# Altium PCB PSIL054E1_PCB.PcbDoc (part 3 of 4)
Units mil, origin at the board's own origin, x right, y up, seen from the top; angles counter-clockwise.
Board outline 2080 x 2700 mil, 8 copper layers (SSTXRX1, GND Plane 1, High Speed, GND Plane 2, Power 1, Power 2, GND Plane 3, SSTXRX2), stack 58.12 mil thick; 247 components, 148 nets, 834 pads, 632 vias.
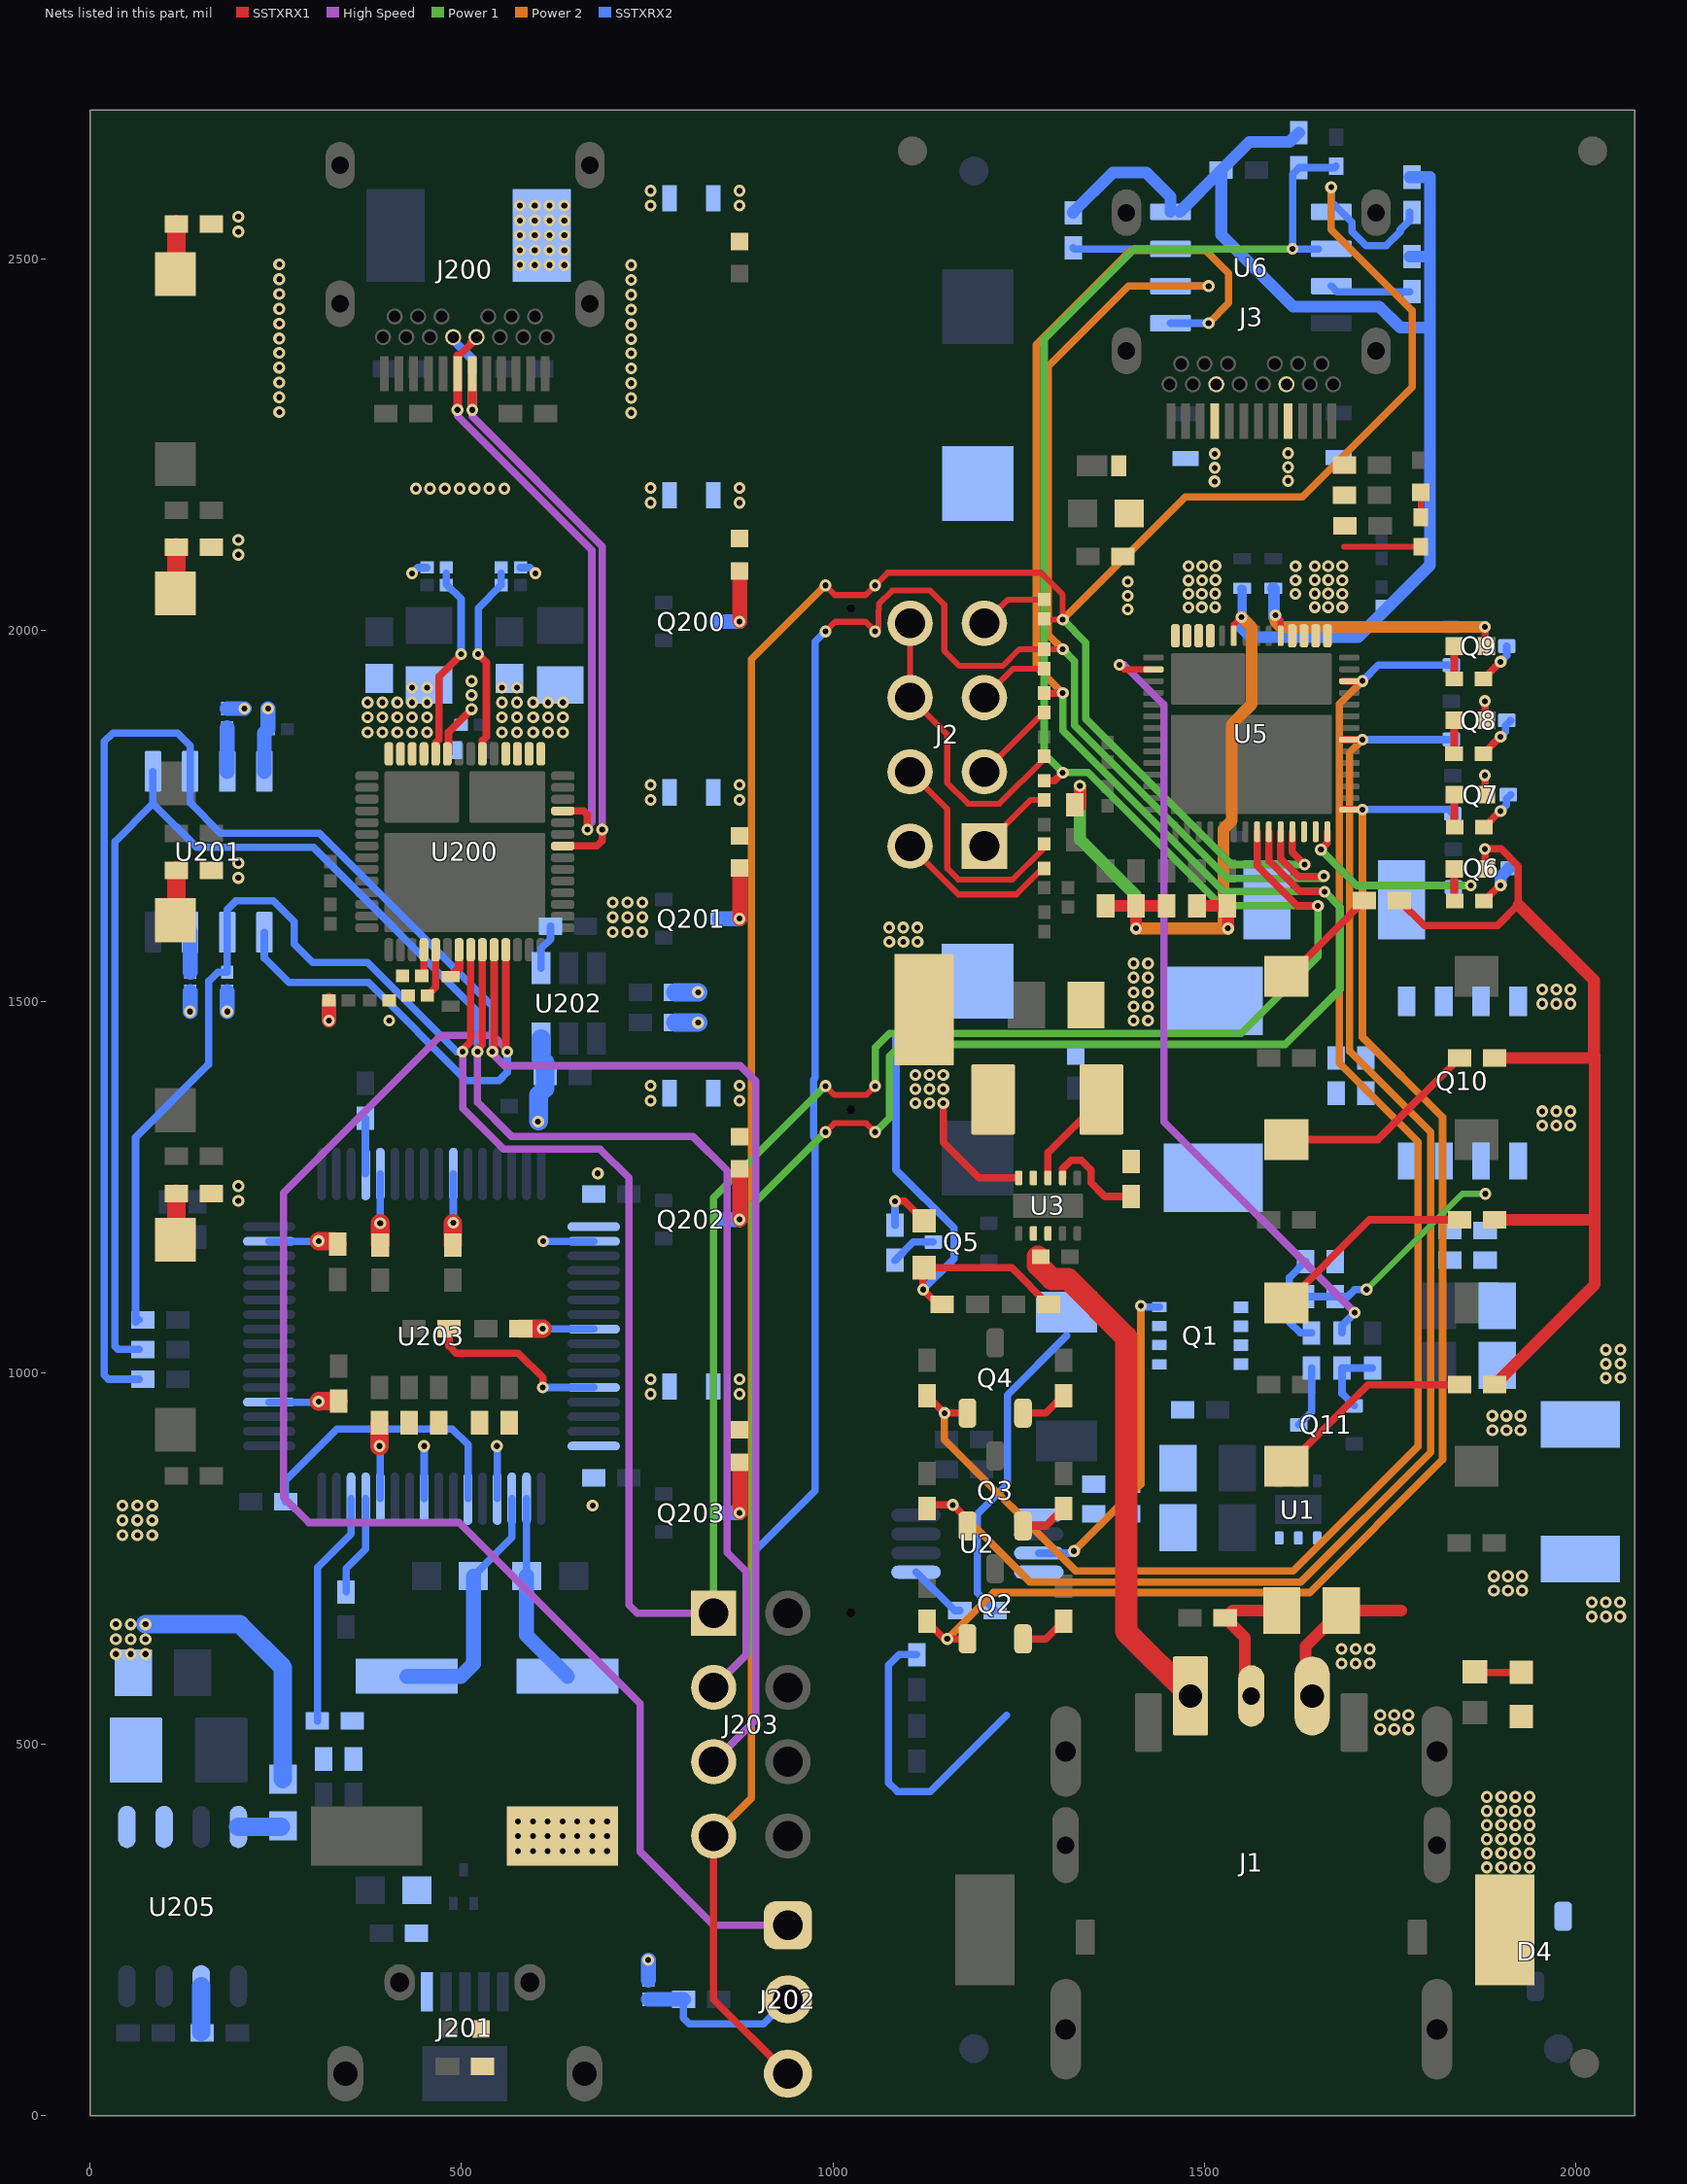
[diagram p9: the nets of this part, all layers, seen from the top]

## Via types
v1: diameter 16, hole 8, SSTXRX1 to SSTXRX2, tented both sides, 581 vias
v2: diameter 19.68, hole 7.87, SSTXRX1 to SSTXRX2, tented both sides, 51 vias

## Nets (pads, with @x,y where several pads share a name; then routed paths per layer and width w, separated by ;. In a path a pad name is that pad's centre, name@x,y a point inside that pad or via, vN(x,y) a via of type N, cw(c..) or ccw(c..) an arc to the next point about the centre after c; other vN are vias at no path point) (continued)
LDO_3V3: C20.1 C23.1 R36.2 R37.2 R38.2 R39.1 R40.1 R41.2 R42.1 R44.1 R45.1 R46.1 R47.2 U5.9 U6.8 | length 2771.1
  SSTXRX1 w8: U5.9@1539.88,1992.15 1539.88,2007.04 v1(1550.1,2017.26)
  SSTXRX1 w16: R36.2@1332.57,1762.63 v1(1332.57,1790.01) ; R37.2@1367.29,1628.64 R38.2@1408.29,1628.64 R46.1@1449.29,1628.64 ; v1(1408.1,1598.26) R38.2@1408.1,1628.45 ; R45.1@1490.29,1628.64 R44.1@1531.29,1628.64 1532.1,1627.83 v1(1532.1,1598.26)
  Power 1 w16: v1(1332.57,1790.01) 1332.57,1718.01 1408.1,1642.48 v1(1408.1,1598.26)
  Power 2 w16: v1(1408.1,1598.26) v1(1532.1,1598.26) 1526.1,1604.26 1526.1,1732.1 1537,1743 1537,1873 1564,1900 1564,2003.36 v1(1550.1,2017.26)
  SSTXRX2 w12: v1(1550.1,2017.26) 1551.1,2018.26 1551.1,2055.26 C23.1@1550.1,2055.26
  SSTXRX2 w16: R41.2@1323.57,2561.63 1323.57,2562.57 1377,2616 1422,2616 1454.73,2583.27 U6.8@1454.73,2563 ; U6.8@1466.94,2563 C20.1@1522.95,2619.01 ; v1(1550.1,2017.26) 1550.1,2003.26 1563.1,1990.26 1707.1,1990.26 1804,2087.16 1804,2407 ; R40.1@1627.57,2669.63 1614.94,2657 1560.94,2657 C20.1@1522.95,2619.01 ; R42.1@1776.57,2502.63 1803.63,2502.63 ; R39.1@1776.57,2609.63 1801.63,2609.63 ; 1804,2610 1804,2407 ; C20.1@1522.95,2619.01 1522.95,2532.05 1619.78,2435.22 1735.78,2435.22 1764,2407 1804,2407
LDO_3V3_SINK: C207.1 C208.1 C213.1 R201.2 R202.2 R203.1 R204.1 R205.2 R206.2 R207.2 R208.2 R209.2 R210.2 R213.2 R214.2 R215.2 R217.2 R219.2 R220.2 R221.2 R223.2 U200.9 U201.8 | length 331.7
  SSTXRX1 w10: U200.9@480.83,1833.2 482.45,1833.2 482.45,1862.31 v1(513.45,1893.31)
  SSTXRX1 w20: v1@321.46,1474.32 R201.2@321.46,1501.31
  SSTXRX2 w10: v1(433.45,2076.31) 441.14,2084 R209.2@453,2084 ; R210.2@579,2084 591.75,2084 v1(599.45,2076.31)
  SSTXRX2 w20: v1(134.45,1486.31) R208.2@134.45,1513.32 ; v1(184.45,1486.31) R206.2@184.45,1513.32 ; R207.2@184.45,1894.3 v1(207.45,1894.31) ; U201.8@234.45,1809.57 C213.1@234.45,1861.31 ; C213.1@239.45,1866.31 v1(239.45,1894.31) ; R205.2@751.45,182.31 v1(751.45,209.32)
  other v1: 754.45,971.31 754.45,991.31 199.45,1231.31 199.45,1251.31 754.45,1366.31 754.45,1386.31 321.45,1474.31 402.45,1474.31 199.45,1666.31 199.45,1686.31 754.45,1771.31 754.45,1791.31 513.45,1912.31 513.45,1931.31 199.45,2101.31 199.45,2121.31 754.45,2171.31 754.45,2191.31 199.45,2536.31 199.45,2556.31
NetC6_2: C6.2 R3.1 U2.5
NetC12_1: C12.1 C13.1 C14.1 Q10.7 Q10.8 R22.2 R24.2
  other v1: 1888.07,922.66 1907.07,922.66 1926.07,922.66 1888,942 1907,942 1926,942 2041,993 2060.34,993.07 2041,1012 2060.34,1012.07 2041,1031 2060.34,1031.07 1955.07,1332.66 1974.07,1332.66 1993.07,1332.66 1955,1352 1974,1352 1993,1352 1955.07,1496.66 1974.07,1496.66 1993.07,1496.66 1955,1516 1974,1516 1993,1516
NetC14_2: C14.2 C15.2 C16.2 Q10.2 Q10.4 R24.1 R25.1 R26.1 R27.2 | length 126.6
  SSTXRX2 w10: C15.2@1636.47,1149.77 1614.66,1127.96 1614.66,1068.28 1629.38,1053.55 R27.2@1644.66,1053.55
NetC15_1: C15.1 Q10.1 Q10.3 R25.2 | length 299.5
  Power 1 w8: v1(1718.66,1111.93) 1847.66,1240.93 v1(1878.66,1240.93)
  SSTXRX2 w10: C15.1@1636.47,1102.53 R25.2@1676.47,1102.53 1693.26,1102.53 1702.66,1111.93 v1(1718.66,1111.93)
NetC16_1: C16.1 Q10.5 Q10.6 R23.1 R26.2
NetC206_1: C206.1 U200.35 | length 40.7
  SSTXRX1 w12: C206.1@485.45,1533.31 496.57,1544.43 U200.35@496.57,1569.42
NetC227_2: C227.2 U203.2 Y200.1 | length 262.1
  SSTXRX2 w10: C227.2@587.4,726.86 U203.2@587.4,830.48
  SSTXRX2 w20: C227.2@587.4,726.86 587.4,646.62 Y200.1@642.71,591.31
NetC228_1: C228.1 J201.1 L200.1
NetC229_2: C229.2 U203.3 Y200.2 | length 340.7
  SSTXRX2 w10: C229.2@515.94,726.31 567.72,778.08 U203.3@567.72,830.48
  SSTXRX2 w20: Y200.2@426.18,591.31 499.45,591.31 515.94,607.8 C229.2@515.94,726.31
NetD2_2: D2.2 R7.2 | length 59.5
  SSTXRX1 w10: R7.2@1867.53,596.53 D2.2@1927,596.53
NetD3_1: D3.1 R8.2 | length 82.4
  SSTXRX1 w10: v1(1083.66,1230.93) 1096.15,1230.93 D3.1@1122.66,1204.43
  SSTXRX2 w10: R8.2@1083.66,1198.55 v1(1083.66,1230.93)
NetD5_2: D5.2 R18.2 | length 42.4
  SSTXRX1 w10: R18.2@1836.79,1635.88 D5.2@1836.79,1678.26
NetD6_2: D6.2 R19.2 | length 43.4
  SSTXRX1 w10: R19.2@1836.79,1734.88 D6.2@1836.79,1778.26
NetD7_2: D7.2 R20.2 | length 44.6
  SSTXRX1 w10: R20.2@1836.79,1833.64 D7.2@1836.79,1878.26
NetD8_2: D8.2 R21.2 | length 44
  SSTXRX1 w10: R21.2@1836.76,1934.26 D8.2@1836.76,1978.23
NetD9_1: D9.1 R61.1 | length 33.7
  SSTXRX1 w8: R61.1@1791.38,2151.68 D9.1@1791.38,2185.35
NetD200_1: D200.1 R200.1
  other v1: 874.45,2571.31 874.45,2591.31
NetD201_1: D201.1 R213.1
  other v1: 874.45,2171.31 874.45,2191.31
NetD201_2: D201.2 Q200.3 | length 85.1
  SSTXRX1 w20: v1(874.45,2011.31) D201.2@874.45,2068.83
  SSTXRX2 w20: Q200.3@846.85,2011.31 v1(874.45,2011.31)
NetD202_1: D202.1 R214.1
  other v1: 874.45,1771.31 874.45,1791.31
NetD202_2: D202.2 Q201.3 | length 86.1
  SSTXRX1 w20: v1(874.45,1611.31) 874.45,1668.83 D202.2@874.45,1669.81
  SSTXRX2 w20: Q201.3@846.85,1611.31 v1(874.45,1611.31)
NetD203_1: D203.1 R220.1
  other v1: 874.45,1366.31 874.45,1386.31
NetD203_2: D203.2 Q202.3 | length 85.1
  SSTXRX1 w20: v1(874.45,1206.31) D203.2@874.45,1263.83
  SSTXRX2 w20: Q202.3@846.85,1206.31 v1(874.45,1206.31)
NetD204_1: D204.1 R221.1
  other v1: 874.45,971.31 874.45,991.31
NetD204_2: D204.2 Q203.3 | length 85.1
  SSTXRX1 w20: v1(874.45,811.31) D204.2@874.45,868.83
  SSTXRX2 w20: Q203.3@846.85,811.31 v1(874.45,811.31)
NetD205_2: D205.2 R234.2
NetJ1_3: J1.3 R1.1 R2.2 | length 196.5
  SSTXRX1 w16: J1.3@1554.66,564.89 1554.66,643.55 R2.2@1528.28,669.93 1538.28,679.93 R1.1@1604.66,679.93
NetJ2_1: J2.1 R53.2 | length 106.3
  SSTXRX1 w8: J2.1@1204,1709 1266.02,1771.02 R53.2@1284.57,1771.02
NetJ2_2: J2.2 R51.2 | length 222
  SSTXRX1 w8: J2.2@1104,1709 1169,1644 1247,1644 1282,1679 R51.2@1284.57,1679
NetJ2_3: J2.3 R55.1 | length 113.7
  SSTXRX1 w8: J2.3@1204,1809 1284.02,1889.02 R55.1@1284.57,1889.02
NetJ2_4: J2.4 R50.2 | length 310.6
  SSTXRX1 w8: J2.4@1104,1809 1154,1759 1154,1679 1169,1664 1242,1664 1284.57,1706.57 R50.2@1284.57,1712.02
NetJ2_5: J2.5 R54.2 | length 96.7
  SSTXRX1 w8: J2.5@1204,1909 1243.02,1948.02 R54.2@1284.57,1948.02
NetJ2_6: J2.6 J2.8 R57.2 | length 406.4
  SSTXRX1 w8: J2.8@1104,2009 J2.6@1104,1909 1154,1859 1154,1794 1182,1766 1224,1766 1284.57,1826.57 R57.2@1284.57,1830.02
NetJ2_7: J2.7 R56.2 | length 93.8
  SSTXRX1 w8: J2.7@1204,2009 1236,2041 R56.2@1284.57,2041
NetL2_1: L2.1 U3.9
NetQ1_4: Q1.4 U2.7 | length 441.3
  Power 2 w10: v1(1324.66,759.93) 1414.66,849.93 v1(1414.66,1089.93)
  SSTXRX2 w10: U2.7@1277.33,757.14 1321.86,757.14 v1(1324.66,759.93) ; v1(1414.66,1089.93) 1416.27,1088.32 Q1.4@1439.54,1088.32
NetQ2_2: Q2.2 R14.2 | length 64.4
  SSTXRX1 w10: Q2.2@1256.06,641.69 1287.04,641.69 R14.2@1310.66,665.31
NetQ3_2: Q3.2 R15.2 | length 64.4
  SSTXRX1 w10: Q3.2@1256.06,793.69 1287.04,793.69 R15.2@1310.66,817.31
NetQ4_2: Q4.2 R16.2 | length 64.4
  SSTXRX1 w10: Q4.2@1256.06,945.69 1287.04,945.69 R16.2@1310.66,969.31
NetQ5_3: Q5.3 R8.1 | length 61.8
  SSTXRX2 w10: R8.1@1083.66,1151.31 1108.28,1175.93 Q5.3@1135.26,1175.93
NetQ6_3: Q6.3 R18.1 | length 58.7
  SSTXRX1 w10: R18.1@1876.78,1635.26 1897.78,1656.26 v1(1899.1,1656.26)
  SSTXRX2 w16: v1(1899.1,1656.26) 1899.1,1667.86 Q6.3@1910.5,1679.26
NetQ7_3: Q7.3 R19.1 | length 59.1
  SSTXRX1 w10: R19.1@1876.78,1734.26 1898.78,1756.26 v1(1899.1,1756.26)
  SSTXRX2 w10: v1(1899.1,1756.26) 1907,1764.16 1907,1772.56 Q7.3@1912.7,1778.26
NetQ8_3: Q8.3 R20.1 | length 60.5
  SSTXRX1 w10: R20.1@1875.78,1833.26 1898.78,1856.26 v1(1899.1,1856.26)
  SSTXRX2 w10: v1(1899.1,1856.26) 1906,1863.16 1906,1871.56 Q8.3@1912.7,1878.26
NetQ9_3: Q9.3 R21.1 | length 57
  SSTXRX1 w10: R21.1@1876.13,1934.26 v1@1899.1,1957.23
  SSTXRX2 w10: v1(1899.1,1957.26) 1907.5,1965.66 Q9.3@1907.5,1978.26
NetQ11_1: Q11.1 R31.1 R32.2 | length 98.6
  SSTXRX2 w10: Q11.1@1702.06,955.52 1685.66,971.92 R31.1@1685.66,1006.31 R32.2@1726.66,1006.31
NetQ11_3: Q11.3 R27.1 | length 83.6
  SSTXRX2 w10: Q11.3@1627.26,929.93 1644.66,947.33 R27.1@1644.66,1006.31
NetR6_1: R6.1 U2.1 | length 80.4
  SSTXRX2 w10: U2.1@1111.98,731.54 1163.59,679.93 R6.1@1171.04,679.93
NetR17_1: R17.1 U3.7 | length 139.4
  SSTXRX1 w10: U3.7@1309.34,1262.33 1309.34,1274.62 1320.66,1285.93 1334.66,1285.93 1347.66,1272.93 1347.66,1255.93 1366.28,1237.31 R17.1@1401.66,1237.31
NetR41_1: R41.1 U6.7 | length 131.7
  SSTXRX2 w10: R41.1@1323.57,2514.39 1324.96,2513 U6.7@1454.73,2513
NetR42_2: R42.2 U6.3 | length 108.5
  SSTXRX2 w10: U6.3@1671.27,2463 1678.88,2455.39 R42.2@1776.57,2455.39
NetR58_1: R58.1 S1.2 | length 146.9
  SSTXRX1 w10: S1.2@1610.7,1533.93 1613.76,1533.93 R58.1@1715.51,1635.68
NetR60_1: R60.1 S2.2 | length 278.9
  SSTXRX1 w10: S2.2@1610.7,1313.93 1734.04,1313.93 R60.1@1844.04,1423.93
NetR63_1: R63.1 S3.2 | length 279.7
  SSTXRX1 w10: S3.2@1610.7,1093.93 1722.7,1205.93 R63.1@1844.04,1205.93
NetR65_1: R65.1 S4.2 | length 278.9
  SSTXRX1 w10: S4.2@1610.7,873.93 1720.7,983.93 R65.1@1844.04,983.93
NetR203_2: R203.2 U200.33 | length 66
  SSTXRX1 w10: R203.2@453.99,1508 465.08,1519.09 U200.33@465.08,1569.42
NetR204_2: R204.2 U200.32 | length 36.3
  SSTXRX1 w10: R204.2@446.44,1534.31 449.33,1537.2 U200.32@449.33,1569.42
NetR207_1: R207.1 U201.7 | length 58.7
  SSTXRX2 w20: U201.7@184.45,1809.57 R207.1@184.45,1868.32
NetR208_1: R208.1 U201.3 | length 53.7
  SSTXRX2 w20: R208.1@134.45,1539.3 U201.3@134.45,1593.04
NetR209_1: R209.1 R211.2 U200.10 | length 265.6
  SSTXRX1 w10: U200.10@465.08,1833.2 465.08,1848.1 469.45,1852.47 469.45,1937.31 v1(499.45,1967.31)
  SSTXRX2 w10: R209.1@479.44,2076.31 479.44,2061.56 499.45,2041.55 v1(499.45,1967.31)
NetR210_1: R210.1 R212.2 U200.6 | length 262.7
  SSTXRX1 w10: v1(522.45,1967.31) 533.45,1956.31 533.45,1856.31 528.07,1850.93 U200.6@528.07,1833.2
  SSTXRX2 w10: v1(522.45,1967.31) 522.45,2029.45 553.46,2060.46 R210.1@553.46,2076.31
NetR215_1: R215.1 S200.2 | length 65.7
  SSTXRX1 w25: S200.2@115.83,2480.64 R215.1@115.83,2546.31
NetR217_1: R217.1 S201.2 | length 60.7
  SSTXRX1 w25: S201.2@115.83,2050.64 R217.1@115.83,2111.31
NetR219_1: R219.1 S202.2 | length 65.7
  SSTXRX1 w25: S202.2@115.83,1610.64 R219.1@115.83,1676.31
NetR223_1: R223.1 S203.2 | length 60.7
  SSTXRX1 w25: S203.2@115.83,1180.64 R223.1@115.83,1241.31
NetR228_1: R228.1 U202.1 | length 62
  SSTXRX2 w10: U202.1@607.05,1544.55 607.05,1571.05 619.83,1583.83 R228.1@619.83,1601.31
NetR229_1: R229.1 U203.6 | length 384.4
  SSTXRX2 w10: R229.1@263.07,826.31 263.07,854.93 332.45,924.31 487.45,924.31 508.66,903.09 U203.6@508.66,830.48
NetR230_1: R230.1 R232.1 R235.2
NetR231_1: R231.1 U203.13 | length 136.5
  SSTXRX2 w10: R231.1@344.45,704.93 344.45,736.31 370.86,762.72 U203.13@370.86,830.48
NetR233_1: R233.1 U203.60 | length 248.7
  SSTXRX1 w10: R233.1@483.07,1059.31 483.07,1035.93 492.69,1026.31 576.45,1026.31 609.45,993.31 v1(609.45,980.31)
  SSTXRX2 w10: v1@609.67,980.09 U203.60@677.95,980.09
NetR236_1: R236.1 U203.36 | length 75.4
  SSTXRX2 w10: R236.1@370.45,1342.69 370.45,1267.91 U203.36@370.86,1267.49
NetR242_1: R242.1 U205.8 | length 57.3
  SSTXRX2 w25: U205.8@199.45,388.59 R242.1@256.73,388.59
NetR244_1: R244.1 U205.2 | length 61.3
  SSTXRX2 w25: R244.1@149.45,112.69 U205.2@149.45,174.02
P3V3: C11.1 C26.1 D5.1 D6.1 D7.1 D8.1 L2.2 R17.2 R58.2 R60.2 R63.2 R65.2 TP3.1 U3.8 U3.10 U5.5 | length 2095.7
  SSTXRX1 w8: v1(1596,2020) 1602.87,2013.13 U5.5@1602.87,1992.15
  SSTXRX1 w10: v1@1148.66,1364.93 1148.66,1310.34 1196.67,1262.33 U3.10@1250.29,1262.33 ; U3.8@1289.66,1262.33 1289.66,1296.1 L2.2@1361.49,1367.93 ; R58.2@1762.75,1635.68 1796.43,1602 1895,1602 1923,1630 1923,1682 1899.74,1705.26 v1(1878.1,1705.26) 1878.1,1682.26 1877.1,1681.26 D5.1@1880.1,1678.26 ; v1(1878.1,1804.26) 1878.1,1780.26 D6.1@1880.1,1778.26 ; v1(1878.1,1904.26) 1878.1,1880.26 D7.1@1880.1,1878.26 ; v1(1878.1,2004.26) 1878.1,1980.26 D8.1@1880.1,1978.26
  SSTXRX1 w16: R65.2@1891.28,983.93 2026,1118.65 2026,1426 2025,1425 ; R63.2@1891.28,1205.93 2025.93,1205.93 ; R60.2@1891.28,1423.93 2023.93,1423.93 2025,1425 ; 1923,1630 2025,1528 2025,1425
  Power 2 w16: v1(1596,2020) 1596,2011.36 1603.1,2004.26 v1(1878.1,2004.26)
  SSTXRX2 w16: C26.1@1593.1,2056.26 1594.1,2055.26 v1@1594.1,2017.26 ; v1@1594,2017.16 v1@1594.1,2017.26 ; v1(1596,2020) 1596,2019.16 v1@1594.1,2017.26
  other v1: 1111,1363 1130,1363 1148.66,1362.93 1111,1382 1130,1382 1148.66,1381.93 1111,1401 1130,1401 1148.66,1400.93
P3V3_SINK: C214.1 C215.1 C216.1 C217.2 C218.2 C222.1 C223.1 C224.1 C225.1 C231.1 C232.1 R225.2 R226.2 R227.2 R242.2 U202.6 U203.4 U203.9 U203.20 U203.31 U203.42 U203.50 U203.56 U205.5 U205.6 | length 1125.7
  SSTXRX1 w25: v1(307.45,961.31) 307.83,961.69 C225.1@334.45,961.69 ; v1(307.45,1177.31) 329.07,1177.31 C224.1@333.45,1172.93 ; C223.1@488.45,1171.93 v1@488.45,1201.31 ; C222.1@580.07,1059.31 v1(609.45,1059.31)
  SSTXRX2 w10: U203.20@240.94,960.4 v1@306.54,960.4 ; U203.31@240.94,1176.94 v1@307.08,1176.94 ; U203.9@449.6,830.48 v1@449.6,901.15 ; v1(488.97,1201.83) U203.42@488.97,1267.49 ; U203.4@548.03,830.48 v1@548.03,900.72 ; v1(609.82,1176.94) U203.50@677.95,1176.94 ; v1@609.93,1058.83 U203.56@677.95,1058.83
  SSTXRX2 w25: v1(74.45,661.31) 201.45,661.31 259.45,603.31 R242.2@259.45,452.8 ; v1@603.68,1338.68 C216.1@603.68,1359 603.68,1374.18 612.38,1382.88 R226.2@612.38,1399 612.38,1418.12 607.05,1423.45 U202.6@607.05,1450.06 ; R227.2@788.07,1471.31 v1(818.45,1471.31) ; R225.2@788.07,1512.31 v1(818.45,1512.31)
  other v1: 34.45,621.31 54.45,621.31 74.45,621.31 34.45,641.31 54.45,641.31 74.45,641.31 34.45,661.31 54.45,661.31 449.45,901.31 547.45,901.31 603,1338
PDO_0: Q6.1 U5.42 | length 273.9
  SSTXRX1 w10: v1(1657.1,1704.26) 1665.86,1713.03 U5.42@1665.86,1728.37
  Power 1 w10: v1(1657.1,1704.26) 1705.36,1656 v1(1859,1656)
  SSTXRX2 w10: Q6.1@1835.7,1653.67 1838.03,1656 v1(1859,1656)
PDO_1: Q2.1 Q7.1 R11.2 U5.43 | length 1901
  SSTXRX1 w10: R11.2@1126.66,665.31 1150.28,641.69 v1(1154,641.69) Q2.1@1181.26,641.69 ; U5.43@1687.35,1758.26 v1(1713.1,1758.26)
  Power 2 w10: v1(1154,641.69) 1216.31,704 1642,704 1821,883 1821,1344 1713.1,1451.9 v1(1713.1,1758.26)
  SSTXRX2 w10: v1(1713.1,1758.26) 1829.11,1758.26 Q7.1@1834.7,1752.67
PDO_2: Q3.1 Q8.1 R12.2 U5.49 | length 1982.5
  SSTXRX1 w10: R12.2@1131.35,822 v1(1161.56,822) 1181.26,802.3 Q3.1@1181.26,793.69 ; U5.49@1686.99,1852.39 v1@1712.97,1852.39
  Power 2 w10: v1(1161.56,822) 1265.56,718 1630,718 1805,893 1805,1323.86 1695.85,1433.01 1695.85,1835.01 v1(1713.1,1852.26)
  SSTXRX2 w10: v1(1713.1,1852.26) Q8.1@1832.29,1852.26
PDO_3: Q4.1 Q9.1 R13.2 U5.54 | length 2122.3
  SSTXRX1 w10: R13.2@1126.66,969.31 v1(1150.28,945.69) Q4.1@1181.26,945.69 ; U5.54@1686.99,1931.13 v1@1712.96,1931.13
  Power 2 w10: v1(1150.28,945.69) 1150.28,909.78 1327.06,733 1620,733 1788,901 1788,1311 1682,1417 1682,1900.16 v1(1713.1,1931.26)
  SSTXRX2 w10: v1(1713.1,1931.26) 1734.51,1952.67 Q9.1@1832.7,1952.67
PP_EXT_EN: R31.2 U5.16 | length 1081.1
  SSTXRX1 w8: v1(1386,1953) 1392.12,1946.88 U5.16@1423.21,1946.88
  High Speed w10: v1(1386,1953) 1392.36,1953 1446,1899.36 1446,1337.59 v1(1702.66,1080.93)
  SSTXRX2 w10: R31.2@1685.66,1053.55 1685.66,1063.93 v1(1702.66,1080.93)
PP_HV: C1.1 C2.1 C7.1 C8.1 C24.1 C25.1 D3.2 L1.2 R4.2 R23.2 U5.1 U5.2 U5.11 U5.12 | length 642.1
  SSTXRX1 w10: R4.2@1147.04,1092.93 1140.51,1092.93 v1(1121.44,1112) 1121.44,1140.22 D3.2@1122.66,1141.43 1240.78,1141.43 C8.1@1290.28,1091.93
  SSTXRX2 w10: 1085,1453 1085,1273 1163,1195 1163,1153.56 v1(1121.44,1112)
  other v1: 1405,1474 1424.34,1474.07 1405,1493 1424.34,1493.07 1405,1512 1424.34,1512.07 1405,1532 1424.34,1532.07 1405,1551 1424.34,1551.07 1076,1580 1095,1580 1114,1580 1075.93,1599.34 1094.93,1599.34 1113.93,1599.34 1478.71,2030.22 1496.8,2030.48 1685.8,2030.48 1514.9,2030.74 1648.9,2030.74 1666.9,2030.74 1478.8,2048.48 1496.9,2048.74 1515,2049 1649,2049 1667,2049 1685.9,2048.74 1478.9,2066.74 1497,2067 1515.1,2067.26 1649.1,2067.26 1667.1,2067.26 1686,2067 1478.9,2085.74 1497,2086 1515.1,2086.26 1649,2086 1667,2086 1685.9,2085.74
PP_HV_SINK: C209.1 C210.1 TP200.1 U200.1 U200.2 U200.11 U200.12
  other v1: 576,356 596,356 616,356 636,356 656,356 676,356 696,356 576,376 596,376 616,376 636,376 656,376 676,376 696,376 576,396 596,396 616,396 636,396 656,396 676,396 696,396 43.45,781.31 63.45,781.31 83.45,781.31 43.45,801.31 63.45,801.31 83.45,801.31 43.45,821.31 63.45,821.31 83.45,821.31 703.45,1593.31 723.45,1593.31 743.45,1593.31 703.45,1613.31 723.45,1613.31 743.45,1613.31 703.45,1633.31 723.45,1633.31 743.45,1633.31 433.45,1862.31 453.45,1862.31 596.45,1862.31 616.45,1862.31 636.45,1862.31 433.45,1882.31 453.45,1882.31 596.45,1882.31 616.45,1882.31 636.45,1882.31 433.45,1902.31 453.45,1902.31 596.45,1902.31 616.45,1902.31 636.45,1902.31 433.45,1922.31 453.45,1922.31
RESETN: R232.2 U203.14 | length 318
  SSTXRX2 w10: R232.2@305.83,531.31 305.83,737.68 351.18,783.04 U203.14@351.18,830.48
SPI_CLK: J203.5 R54.1 R237.2 U5.38 U6.6 U200.38 U201.6 | length 6519.9
  SSTXRX1 w8: v1(990,1998) 1003,2011 1044,2011 v1(1057,1998) 1061.64,2002.64 1061.64,2026.55 1062,2026.91 1062,2035 1080,2053 1131,2053 1150,2034 1150,1972 1170,1952 1229,1952 1251.01,1974.01 v1(1309.57,1974.01)
  SSTXRX1 w10: v1(541.45,1432.31) 543.82,1434.68 U200.38@543.82,1569.42 ; U5.38@1602.87,1728.37 1602.87,1692.13 1626.32,1668.68 1628.05,1668.68 1628.47,1668.26 1660.71,1668.26 v1(1661.13,1668.68)
  High Speed w10: v1(541.45,1432.31) 541.45,1429.68 557.82,1413.31 875.06,1413.31 896,1392.37 896,532.86 J203.5@839.45,476.31
  Power 1 w10: v1(1309.57,1974.01) 1325.57,1958.01 1325.57,1871.43 1531.32,1665.68 1658.13,1665.68 v1(1661.13,1668.68)
  Power 2 w10: v1(1309.57,1974.01) 1290,1993.58 1290,2355 1398,2463 v1(1506,2463)
  SSTXRX2 w10: R237.2@65.83,991.31 24.45,991.31 19,996.75 19,1849.86 30.45,1861.31 117.45,1861.31 134.45,1844.31 U201.6@134.45,1809.57 134.45,1767.31 175.45,1726.31 308.45,1726.31 541.45,1493.31 v1(541.45,1432.31) ; J203.5@839.45,476.31 891,527.86 891,756 976,841 976,1315.37 974,1317.37 974,1394.63 976,1396.63 976,1984 v1(990,1998) ; U6.6@1454.73,2463 v1(1506,2463)
SPI_CSZ: J202.2 R205.1 R240.2 | length 230
  SSTXRX2 w10: R240.2@798.83,156.31 798.83,131.17 806.69,123.31 906.45,123.31 J202.2@939.45,156.31
  SSTXRX2 w20: R205.1@751.45,156.32 R240.2@798.83,156.31
SPI_CSZ_SINK: J202.1 U200.39 U201.1 | length 2444.1
  SSTXRX1 w10: U200.39@559.57,1569.42 559.57,1434.19 v1(561.45,1432.31)
  High Speed w10: v1(561.45,1432.31) 561.45,1434.93 542.07,1454.31 472.45,1454.31 260.45,1242.31 260.45,832.31 294.45,798.31 496.45,798.31 740.45,554.31 740.45,355.31 839.45,256.31 J202.1@939.45,256.31
  SSTXRX2 w10: U201.1@234.45,1593.04 234.45,1558.31 267.45,1525.31 374.45,1525.31 506.45,1393.31 550.45,1393.31 561.45,1404.31 v1(561.45,1432.31)
SPI_CSZ_SOURCE: J202.3 J203.7 R39.2 R56.1 U5.39 U6.1 | length 4189.5
  SSTXRX1 w8: v1@990,2059.74 1002.74,2047 1044,2047 v1(1057,2060) 1074,2077 1280,2077 1309.57,2047.43 v1(1309.57,2014.01) 1284.57,2014 R56.1@1281,2014
  SSTXRX1 w10: J203.7@839.45,376.31 839.45,156.31 J202.3@939.45,56.31 ; v1@990,2059.74 v1(990,2060) ; U5.39@1618.62,1728.37 1618.62,1700.74 v1(1635.1,1684.26)
  Power 1 w10: v1(1309.57,2014.01) 1340.57,1983.01 1340.57,1880.43 1536.74,1684.26 v1(1635.1,1684.26)
  Power 2 w10: J203.7@839.45,376.31 890.45,427.31 890.45,1960.45 v1(990,2060) ; v1(1309.57,2014.01) 1474.56,2179 1632,2179 1780,2327 1780,2430 1671,2539 v1(1671,2596)
  SSTXRX2 w10: v1(1671,2596) 1671,2577 1699.08,2548.92 1699.08,2536.56 1718.13,2517.51 1745.09,2517.51 1764.15,2536.56 1764.15,2539.15 1776.57,2551.57 R39.2@1776.57,2562.39
SPI_MISO: J203.1 R40.2 R43.2 R53.1 R206.1 R239.2 U5.36 U6.2 U200.36 U201.2 | length 5608.9
  SSTXRX1 w8: v1(990,1386) 1002,1374 1045,1374 v1(1057,1386)
  SSTXRX1 w10: v1(501.45,1432.31) 501.45,1434.93 512.32,1445.81 U200.36@512.32,1569.42 U200.36@512.45,1569.42 ; R53.1@1284.57,1797 1298.56,1797 v1(1309.57,1808.01) ; U5.36@1571.37,1728.37 1571.37,1682.63 1625.32,1628.68 v1(1653.13,1628.68)
  High Speed w10: v1(501.45,1432.31) 501.45,1356.31 556.45,1301.31 686.45,1301.31 725.45,1262.31 725.45,687.31 736.45,676.31 J203.1@839.45,676.31
  Power 1 w10: J203.1@839.45,676.31 839.45,1235.45 v1(990,1386) ; v1(1057,1386) 1057,1438 1076,1457 1550,1457 1653.13,1560.13 v1(1653.13,1628.68) 1522.9,1628.68 1343.57,1808.01 v1(1309.57,1808.01) 1284.57,1833.01 1284.57,2391.57 1406,2513 v1(1619,2513)
  SSTXRX2 w10: R239.2@65.83,1071.31 64.31,1071.31 61,1068 61,1316.86 159.45,1415.31 159.45,1527.06 171.69,1539.3 R206.1@184.45,1539.3 U201.2@184.45,1593.04 184.45,1623.31 196.45,1635.31 246.45,1635.31 274.45,1607.31 274.45,1577.31 299.45,1552.31 373.45,1552.31 493.45,1432.31 v1(501.45,1432.31) ; U6.2@1654,2513 v1(1619,2513) 1619,2613.82 R40.2@1627.57,2622.39 1675.63,2622.39 R43.2@1677.57,2624.32
SPI_MOSI: J203.3 R55.2 R238.2 U5.37 U6.5 U200.37 U201.5 | length 6111.6
  SSTXRX1 w8: v1(990,1324) 1002,1336 1045,1336 v1(1057,1324)
  SSTXRX1 w10: v1(521.45,1432.31) 521.45,1434.93 528.07,1441.56 U200.37@528.07,1569.42 ; R55.2@1284.57,1915 v1(1309.57,1915.01) ; U5.37@1587.12,1728.37 1587.12,1689.49 1628.94,1647.68 v1(1662.13,1647.68)
  High Speed w10: v1(521.45,1432.31) 521.45,1364.31 567.45,1318.31 811.45,1318.31 857.45,1272.31 857.45,758.31 883,732.75 883,619.86 J203.3@839.45,576.31
  Power 1 w10: J203.3@839.45,576.31 893,629.86 893,1227 v1(990,1324) ; v1(1057,1324) 1076,1343 1076,1426 1092,1442 1609,1442 1683,1516 1683,1626.81 v1(1662.13,1647.68) 1526.32,1647.68 1309.57,1864.43 v1(1309.57,1915.01)
  Power 2 w10: v1(1309.57,1915.01) 1274,1950.58 1274,2384 1401,2511 1502,2511 1533,2480 1533,2440 v1(1506,2413)
  SSTXRX2 w10: R238.2@65.83,1031.31 37.45,1031.31 33,1035.75 33,1714.86 84.45,1766.31 ; U201.5@84.45,1809.57 84.45,1766.31 ; v1(521.45,1432.31) 521.45,1486.31 300.45,1707.31 143.45,1707.31 84.45,1766.31 ; U6.5@1454.73,2413 v1(1506,2413)
SW_Node_VARDC: D1.1 L1.1 Q1.5 Q1.6 Q1.7 Q1.8 R6.2 | length 429.5
  SSTXRX2 w10: R6.2@1218.28,679.93 1194.66,703.55 1194.66,809.93 1234.93,850.21 1234.93,970.21 1314.66,1049.93
SWD_CLK: U5.40
SWD_DATA: U5.41
SYS_PWR: C3.1 C4.1 C5.1 C6.1 C10.1 D2.1 D4.1 D4.2 J1.1 J1.2 Q1.1 Q1.2 Q1.3 R1.2 R3.2 R5.2 R22.1 TP1.1 U1.4 U1.5 U1.6 U2.8 U3.2 U3.3 | length 1312.9
  SSTXRX1 w16: J1.2@1636.55,564.89 1636.55,631.82 R1.2@1684.66,679.93 1765.13,679.93
  SSTXRX1 w30: C10.1@1276.04,1155.93 1276.04,1145.31 1295.22,1126.12 1316.88,1126.12 1395,1048 1395,651.5 J1.1@1481.61,564.89
  SSTXRX2 w10: R5.2@1113,620.41 1089.41,620.41 1075,606 1075,448 1087,436 1131,436 1234,539
  other v1: 1880.66,333.93 1900,334 1919,334 1938,334 1880.66,352.93 1900,353 1919,353 1938,353 1880.66,371.93 1900,372 1919,372 1938,372 1880.66,390.93 1900,391 1919,391 1938,391 1880.66,409.93 1900,410 1919,410 1938,410 1880.66,428.93 1900,429 1919,429 1938,429 1737,520 1756,520 1775,520 1736.93,539.34 1755.93,539.34 1774.93,539.34 1685.07,608.66 1704.07,608.66 1723.07,608.66 1685,628 1704,628 1723,628 2022.07,671.66 2041.07,671.66 2060.07,671.66 2022,691 2041,691 2060,691 1890.07,706.66 1909.07,706.66 1928.07,706.66 1890,726 1909,726 1928,726
USB_N: J200.A7 J200.B7 U200.53 | length 807.6
  SSTXRX1 w10: 494.6,2368.79 496.59,2368.79 512.38,2384.57 512.38,2386.56 518.82,2393 J200.B7@521,2393 ; U200.53@636.34,1756.43 664.33,1756.43 669.45,1751.31 v1(669.45,1731.31)
  SSTXRX1 w12: v1@494.6,2296.46 J200.A7@494.6,2344.77 494.6,2368.79
  High Speed w10: v1(494.45,2296.31) 494.45,2288.31 675.45,2107.31 675.45,1741.35 669.45,1735.35 v1(669.45,1731.31)
USB_P: J200.A6 J200.B6 U200.50 | length 865.6
  SSTXRX1 w10: U200.50@636.34,1709.18 682.32,1709.18 689.45,1716.31 v1(689.45,1731.31)
  SSTXRX1 w12: v1@514.29,2296.46 J200.A6@514.29,2344.77
  High Speed w10: v1(514.45,2296.31) 514.45,2287.62 689.45,2112.62 v1(689.45,1731.31)
  SSTXRX2 w12: J200.B6@488.7,2394.38 488.7,2390.3 514.45,2364.55 v1(514.45,2296.31)
VBUS: C21.1 C27.1 C28.1 C29.1 C30.1 D10.1 J3.A4 J3.A9 J3.B4 J3.B9 R61.2 U5.3 U5.4 U5.13 U5.14 | length 103.1
  SSTXRX1 w8: 1688.31,2112.31 R61.2@1791.38,2112.31
  other v1: 1396.9,2027.74 1397,2046 1622.9,2048.74 1397,2065 1623,2067 1623,2086 1514,2200 1612.9,2200.74 1514.1,2218.26 1613,2219 1514.1,2237.26 1613,2238
VBUS_SINK: C200.1 C201.1 F200.1 R200.2 U200.3 U200.4 U200.13 U200.14
  other v1: 373.45,1862.31 393.45,1862.31 413.45,1862.31 554.45,1862.31 574.45,1862.31 373.45,1882.31 393.45,1882.31 413.45,1882.31 554.45,1882.31 574.45,1882.31 373.45,1902.31 393.45,1902.31 413.45,1902.31 554.45,1902.31 574.45,1902.31 554.45,1922.31 574.45,1922.31 438.45,2190.31 457.45,2190.31 477.45,2190.31 497.45,2190.31 517.45,2190.31 537.45,2190.31 557.45,2190.31 728.45,2292.31 254.45,2293.31 728.45,2312.31 254.45,2313.31 728.45,2332.31 254.45,2333.31 728.45,2352.31 254.45,2353.31 728.45,2372.31 254.45,2373.31 728.45,2391.31 254.45,2392.31 728.45,2411.31 254.45,2412.31 728.45,2431.31 254.45,2432.31 728.45,2451.31 254.45,2452.31 728.45,2471.31 254.45,2472.31 578.44,2491.31 598.45,2491.31 618.45,2491.31 638.45,2491.31 728.45,2491.31 254.45,2492.31 578.44,2511.31 598.45,2511.31 618.45,2511.31 638.45,2511.31 578.44,2531.31 598.45,2531.31 618.45,2531.31 638.45,2531.31 578.44,2551.31 598.45,2551.31 618.45,2551.31 638.45,2551.31 578.44,2571.31 598.45,2571.31 618.45,2571.31 638.45,2571.31 754.45,2571.31 754.45,2591.31
VREGOUT: C219.1 C220.1 C221.1 C226.1 U203.12 U203.37 U203.49 U203.64 | length 196.6
  SSTXRX1 w25: v1(389.45,901.31) C221.1@389.45,932.69 ; C220.1@390.45,1171.93 v1(390.45,1201.31)
  SSTXRX2 w10: U203.12@390.55,830.48 v1@390.55,900.2 ; v1@390.55,1201.41 U203.37@390.55,1267.49
  other v1: 676.45,821.31 683.45,1268.31
pads on no net: FID1.1 FID2.1 FID3.1 FID4.1 FID5.1 FID6.1 J3.A2 J3.A3 J3.A8 J3.A10 J3.A11 J3.B2 J3.B3 J3.B8 J3.B10 J3.B11 J200.A2 J200.A3 J200.A8 J200.A10 J200.A11 J200.B2 J200.B3 J200.B8 J200.B10 J200.B11 J201.4 SH-J1.0 U1.7@1608.94,815.93 U1.7@1644.37,815.93 U3.11@1264.46,1224.93 U3.11@1314.85,1224.93 U5.30 U5.31 U5.48 U5.57@1594.01,1934.08 U5.57@1647.16,1934.08 U5.58@1478.85,1934.08 U5.58@1532,1934.08 U5.59@1485.55,1786.05 U5.59@1485.55,1851.8 U5.59@1537.52,1786.05 U5.59@1537.52,1851.8 U5.59@1589.48,1786.05 U5.59@1589.48,1851.8 U5.59@1641.45,1786.05 U5.59@1641.45,1851.8 U200.5 U200.22 U200.23 U200.25 U200.29 U200.30 U200.31 U200.34 U200.40 U200.48 U200.49 U200.54 U200.55 U200.57@534.96,1775.13 U200.57@588.11,1775.13 U200.58@419.8,1775.13 U200.58@472.95,1775.13 U200.59@426.49,1627.09 U200.59@426.49,1692.84 U200.59@478.46,1627.09 U200.59@478.46,1692.84 U200.59@530.43,1627.09 U200.59@530.43,1692.84 U200.59@582.4,1627.09 U200.59@582.4,1692.84 U203.21 U203.22 U203.23 U203.24 U203.29 U203.30 U203.32 U203.33 U203.34 U203.38 U203.39 U203.40 U203.41 U203.43 U203.44 U203.45 U203.46 U203.48 U203.52 U203.53 U203.54 U203.55 U203.57 U203.58 U203.59 U205.7

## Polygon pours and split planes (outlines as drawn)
GND on SSTXRX2 "SSTXRX2_GND_P192" (solid, remove dead copper, pour order 192): 0,2700 2080,2700 2080,0 0,0
SW_Node_VARDC on SSTXRX2 "SSTXRX2_SW_NODE_VARDC_P010" (solid, remove dead copper, pour order 10): 1244.66,979.93 1244.66,1179.93 1378.41,1313.68 1581.13,1313.68 1581.13,1016.4 1544.66,979.93 1484.66,979.93 1464.66,999.93 1464.66,1099.93 1454.66,1109.93 1404.66,1109.93 1384.66,1089.93 1384.66,979.93
SYS_PWR on SSTXRX2 "SSTXRX2_SYS_PWR_P008" (solid, remove dead copper, pour order 8): 1204.66,509.93 1664.66,509.93 1664.66,599.93 1494.66,769.93 1494.66,969.93 1484.66,969.93 1454.66,999.93 1454.66,1079.93 1394.66,1079.93 1394.66,982.21 1374.66,962.21 1374.66,779.93 1334.66,739.93 1244.66,739.93 1204.66,699.93
PP_HV on SSTXRX2 "SSTXRX2_PP_HV_P014" (solid, remove dead copper, pour order 14): 1055,1414.68 1055,1607.93 1342.66,1607.93 1404.66,1669.93 1614.66,1669.93 1614.66,1484.79 1544.55,1414.68
NetC6_2 on SSTXRX2 "SSTXRX2_NETC6_2_P018" (solid, remove dead copper, pour order 18): 1244.66,799.93 1324.66,799.93 1334.66,789.93 1374.66,789.93 1374.66,869.93 1284.66,869.93 1244.66,829.93
SYS_PWR on SSTXRX2 "SSTXRX2_SYS_PWR_P020" (solid, remove dead copper, pour order 20): 1514.66,739.93 1574.66,739.93 1594.66,759.93 1594.66,789.93 1804.66,789.93 1814.66,799.93 2072,799.93 2072,607.28 2014.66,549.93 1818.18,549.93 1778.18,509.93 1514.66,509.93
NetC12_1 on SSTXRX2 "SSTXRX2_NETC12_1_P022" (solid, remove dead copper, pour order 22): 1884.66,1529.93 2004.66,1529.93 2072,1462.59 2072,889.93 1894.66,889.93 1864.66,919.93 1864.66,1069.93 1854.66,1079.93 1854.66,1203.93 1928.66,1203.93 1952.13,1227.4 1952.13,1310.68 1942.88,1319.93 1884.66,1319.93
NetC15_1 on SSTXRX2 "SSTXRX2_NETC15_1_P002" (solid, remove dead copper, pour order 2): 1947.66,1309.93 1947.66,1236.93 1920.66,1209.93 1820.12,1209.93 1797.66,1232.39 1797.66,1309.93 1837.66,1309.93 1837.66,1259.93 1844.66,1252.93 1900.66,1252.93 1907.66,1259.93 1907.66,1309.93
NetC14_2 on SSTXRX2 "SSTXRX2_NETC14_2_P006" (solid, remove dead copper, pour order 6): 1887.15,1259.52 1887.15,1319.52 1877.15,1329.52 1777.15,1329.52 1757.15,1309.52 1757.15,1259.52 1797.15,1259.52 1797.15,1309.52 1847.15,1309.52 1847.15,1259.52
NetC14_2 on SSTXRX2 "SSTXRX2_NETC14_2_P024" (solid, remove dead copper, pour order 24): 1587.66,1129.93 1587.66,1329.93 1657.66,1399.93 1737.66,1399.93 1737.66,1349.93 1757.66,1329.93 1777.66,1329.93 1777.66,1219.93 1787.66,1209.93 1850,1209.93 1850,1139.93 1747.66,1139.93 1737.66,1129.93
NetC16_1 on SSTXRX2 "SSTXRX2_NETC16_1_P026" (solid, remove dead copper, pour order 26): 1899.66,1339.93 1899.66,1718.93 1888.66,1729.93 1698.38,1729.93 1652.66,1684.21 1652.66,1406.93 1749.66,1406.93 1749.66,1339.93
PP_HV on SSTXRX2 "SSTXRX2_PP_HV_P028" (solid, remove dead copper, pour order 28): 1614.66,1529.93 1656.66,1571.93 1656.66,1736.93 1624.66,1736.93 1624.66,1813.34 1425.07,2012.93 1055,2012.93 1055,1529.93
PP_HV on SSTXRX2 "SSTXRX2_PP_HV_P038" (solid, remove dead copper, pour order 38): 1435.13,1969.68 1711.13,1969.68 1711.13,2256 1055,2256 1055,1969.68
SYS_PWR on SSTXRX2 "SSTXRX2_SYS_PWR_P064" (solid, pour order 64): 2072,630.93 2072,313 2000,241 1833.66,241 1833.66,544.93 1808.66,569.93 1808.66,630.93
GND on SSTXRX2 "SSTXRX2_GND_P000" (solid, remove dead copper, pour order 0): 1605,2080 1539,2080 1539,2116 1550,2127 1594,2127 1605,2116
VREGOUT on SSTXRX2 "SSTXRX2_VREGOUT_P154" (solid, remove dead copper, pour order 154): 693.45,878.31 713.45,898.31 713.45,903.31 711.45,905.31 647.45,905.31 647.45,829.31 665.45,811.31 685.45,811.31 693.45,819.31
VREGOUT on SSTXRX2 "SSTXRX2_VREGOUT_P152" (solid, remove dead copper, pour order 152): 693.45,1222.31 712.45,1203.31 712.45,1195.31 708.45,1191.31 647.45,1191.31 642.45,1196.31 642.45,1250.31 671.45,1279.31 688.45,1279.31 693.45,1274.31
NetR230_1 on SSTXRX2 "SSTXRX2_NETR230_1_P150" (solid, remove dead copper, pour order 150): 302.45,495.31 325.45,495.31 338.45,508.31 338.45,540.31 342.45,544.31 368.45,544.31 371.45,541.31 371.45,467.31 367.45,463.31 306.45,463.31 302.45,467.31
P3V3_SINK on SSTXRX2 "SSTXRX2_P3V3_SINK_P148" (solid, remove dead copper, pour order 148): 112.45,535.31 97.45,550.31 97.45,664.31 87.45,674.31 23.45,674.31 13.45,664.31 13.45,376.31 28.45,361.31 29.45,362.31 106.45,362.31 112.45,368.31
F_VBUS on SSTXRX2 "SSTXRX2_F_VBUS_P146" (solid, remove dead copper, pour order 146): 396.45,285.31 392.45,281.31 356.45,281.31 281.45,206.31 125.45,206.31 113.45,194.31 113.45,152.31 103.45,142.31 74.45,142.31 74.45,130.31 66.45,122.31 66.45,101.31 63.45,98.31 37.45,98.31 34.45,101.31 34.45,341.31 47.45,354.31 277.45,354.31 293.45,370.31 293.45,445.31 298.45,450.31 325.45,450.31 330.45,445.31 330.45,349.31 355.45,324.31 393.45,324.31 396.45,321.31
NetC228_1 on SSTXRX2 "SSTXRX2_NETC228_1_P144" (solid, remove dead copper, pour order 144): 460.45,140.31 460.45,321.31 457.45,324.31 419.45,324.31 417.45,322.31 417.45,287.31 422.45,282.31 422.45,227.31 445.45,204.31 445.45,140.31
FUSE_VBUS on SSTXRX2 "SSTXRX2_FUSE_VBUS_P142" (solid, remove dead copper, pour order 142): 576.45,2379.85 576.45,2339.31 580.63,2335.13 678.27,2335.13 679.45,2336.31 739.45,2276.31 739.45,2116.31 715.45,2092.31 38.45,2092.31 0,2130.75 0,2656.86 43.14,2700 455.75,2700 494.45,2661.31 494.45,2466.31 474.45,2446.31 414.45,2446.31 324.45,2356.31 324.45,2341.31 329.45,2336.31 424.45,2336.31 427.45,2339.31 427.45,2363.31 454.45,2363.31 468.66,2349.09 468.66,2297.09 479.45,2286.31 540.23,2286.31 540.45,2343.85
VBUS_SINK on SSTXRX2 "SSTXRX2_VBUS_SINK_P140" (solid, remove dead copper, pour order 140): 418.45,1855.31 418.45,1954.31 416.45,1956.31 375.45,1956.31 364.45,1945.31 364.45,1859.31 371.45,1852.31 415.45,1852.31
PP_HV_SINK on SSTXRX2 "SSTXRX2_PP_HV_SINK_P138" (solid, remove dead copper, pour order 138): 425.45,1856.31 425.45,1934.31 446.45,1955.31 482.45,1955.31 484.45,1953.31 484.45,1878.31 459.45,1853.31 428.45,1853.31
VBUS_SINK on SSTXRX2 "SSTXRX2_VBUS_SINK_P136" (solid, remove dead copper, pour order 136): 582.45,1855.31 582.45,1951.31 578.45,1955.31 545.45,1955.31 545.45,1856.31 548.45,1853.31 580.45,1853.31
PP_HV_SINK on SSTXRX2 "SSTXRX2_PP_HV_SINK_P134" (solid, remove dead copper, pour order 134): 588.45,1854.31 588.45,1933.31 610.45,1955.31 647.45,1955.31 649.45,1953.31 649.45,1880.31 623.45,1854.31
FUSE_VBUS on SSTXRX2 "SSTXRX2_FUSE_VBUS_P132" (solid, remove dead copper, pour order 132): 576.45,2339.31 544.45,2339.31 540.45,2343.31 540.45,2400.31 545.45,2405.31 557.45,2405.31 576.45,2386.31
FUSE_VBUS on SSTXRX2 "SSTXRX2_FUSE_VBUS_P130" (solid, remove dead copper, pour order 130): 427.45,2363.31 446.45,2382.31 446.45,2401.31 450.45,2405.31 464.45,2405.31 468.45,2401.31 468.45,2349.31 458.45,2339.31 427.45,2339.31
FUSE_VBUS on SSTXRX2 "SSTXRX2_FUSE_VBUS_P128" (solid, remove dead copper, pour order 128): 381.44,2700 700.75,2700 739.45,2661.31 739.45,2116.31 714.45,2116.31 679.45,2151.31 679.45,2361.31 594.45,2446.31 381.44,2446.31
LDO_3V3_SINK on SSTXRX2 "SSTXRX2_LDO_3V3_SINK_P126" (solid, remove dead copper, pour order 126): 521.45,1888.31 518.45,1885.31 510.45,1885.31 508.45,1883.31 508.45,1822.31 505.45,1819.31 486.45,1819.31 485.45,1820.31 485.45,1876.31 503.45,1894.31 503.45,1937.31 508.45,1942.31 516.45,1942.31 521.45,1937.31
GND on SSTXRX1 "SSTXRX1_GND_P186" (solid, remove dead copper, pour order 186): 0,2700 2080,2700 2080,0 0,0
P3V3 on SSTXRX1 "SSTXRX1_P3V3_P066" (solid, remove dead copper, pour order 66): 1229.79,1563.93 1229.79,1423.34 1229.14,1424 1160,1424 1160,1563.93
P3V3 on SSTXRX1 "SSTXRX1_P3V3_P056" (solid, remove dead copper, pour order 56): 1418,1268 1418,1476 1330,1564 1226.66,1564 1226.66,1425.34 1384,1268
PP_HV on SSTXRX1 "SSTXRX1_PP_HV_P034" (solid, remove dead copper, pour order 34): 1642.1,1975.26 1670.1,1975.26 1695.1,2000.26 1695.1,2094.26 1647.1,2094.26 1640.1,2087.26 1640.1,2014.26 1642.1,2012.26
PP_HV on SSTXRX1 "SSTXRX1_PP_HV_P036" (solid, remove dead copper, pour order 36): 1478.1,1976.26 1478.1,2017.26 1471.1,2024.26 1471.1,2093.26 1524.1,2093.26 1524.1,2025.26 1517,2018.16 1517,1976.26
VBUS on SSTXRX1 "SSTXRX1_VBUS_P040" (solid, remove dead copper, pour order 40): 1709,1976.26 1709,2149 1675.74,2182.26 1422.1,2182.26 1372.1,2132.26 1372.1,2006.26 1402.1,1976.26 1473.1,1976.26 1475.1,1978.26 1475.1,2014.26 1468.1,2021.26 1468.1,2096.26 1470.1,2098.26 1524.1,2098.26 1603.1,2019.26 1603.1,1976.26
VBUS on SSTXRX1 "SSTXRX1_VBUS_P042" (solid, pour order 42): 1529.14,2095.26 1529.14,2019.26 1607.14,2019.26 1615.64,2027.76 1548.14,2095.26
VBUS on SSTXRX1 "SSTXRX1_VBUS_P052" (solid, remove dead copper, pour order 52): 1709,2312.36 1614.1,2407.26 1614.1,2507.26 1437.1,2507.26 1437.1,2349.26 1372.1,2284.26 1372.1,2132.26 1709,2132.26
NetL2_1 on SSTXRX1 "SSTXRX1_NETL2_1_P054" (solid, remove dead copper, pour order 54): 1279.66,1251.93 1279.66,1383.93 1245.66,1417.93 1182.66,1417.93 1182.66,1321.93 1189.66,1314.93 1254.66,1314.93 1260.66,1308.93 1260.66,1251.93
SYS_PWR on SSTXRX1 "SSTXRX1_SYS_PWR_P030" (solid, remove dead copper, pour order 30): 1365,732 2072,732 2072,636 1914,478 1365,478
PP_HV_SINK on SSTXRX1 "SSTXRX1_PP_HV_SINK_P122" (solid, remove dead copper, pour order 122): 106.45,835.31 151.45,790.31 152.45,791.31 571.45,791.31 571.45,292.31 570.45,291.31 55.45,291.31 4.45,342.31 4.45,809.31 30.45,835.31
PP_HV_SINK on SSTXRX1 "SSTXRX1_PP_HV_SINK_P120" (solid, remove dead copper, pour order 120): 755.45,1548.86 797,1507.31 797,292.31 318.45,292.31 287.99,322.76 287.99,565.85 632,909.86 632,1487.86 693.45,1549.31 693.45,1627.31 717.45,1651.31 752.45,1651.31 755.45,1648.31
LDO_3V3_SINK on SSTXRX1 "SSTXRX1_LDO_3V3_SINK_P118" (solid, remove dead copper, pour order 118): 393.45,1524.31 411.45,1542.31 429.45,1542.31 429.45,1525.31 437,1517.75 437,1482.86 417.45,1463.31 396.45,1463.31 393.45,1466.31
P3V3_SINK on SSTXRX1 "SSTXRX1_P3V3_SINK_P116" (solid, remove dead copper, pour order 116): 576.26,947.81 576.45,947.62 576.45,900.81 568.45,892.81 520.45,892.81 512.45,900.81 512.64,901 512.64,947 514.45,948.81 576.26,948.81
P3V3_SINK on SSTXRX1 "SSTXRX1_P3V3_SINK_P114" (solid, remove dead copper, pour order 114): 481.26,947.31 481.45,947.12 481.45,900.31 473.45,892.31 425.45,892.31 417.45,900.31 417.64,900.5 417.64,946.5 419.45,948.31 481.26,948.31
VBUS_SINK on SSTXRX1 "SSTXRX1_VBUS_SINK_P112" (solid, remove dead copper, pour order 112): 604.45,2461.31 604.45,2676.31 239.45,2676.31 219.45,2656.31 219.45,1864.31 257.45,1826.31 334.45,1903.31 334.45,2356.31 419.45,2441.31 584.45,2441.31
VBUS_SINK on SSTXRX1 "SSTXRX1_VBUS_SINK_P110" (solid, remove dead copper, pour order 110): 569.45,2676.31 831.69,2676.31 849.45,2658.55 849.45,1905.31 793.45,1849.31 679.45,1849.31 679.45,2346.31 574.45,2451.31 569.45,2456.31
VBUS_SINK on SSTXRX1 "SSTXRX1_VBUS_SINK_P108" (solid, remove dead copper, pour order 108): 599.45,2263.31 676.49,2263.31 676.49,2603.35 729.45,2656.31 754.45,2656.31 783.45,2627.31 783.45,1922.31 710.45,1849.31 599.45,1849.31
VBUS_SINK on SSTXRX1 "SSTXRX1_VBUS_SINK_P106" (solid, remove dead copper, pour order 106): 599.45,2263.31 713.45,2263.31 743.45,2233.31 743.45,1945.31 714.45,1916.31 588.45,1916.31 583.45,1911.31 583.45,1893.31 545.45,1893.31 545.45,1963.31 519.45,1989.31 465.45,1989.31 416.45,1940.31 416.45,1826.31 257.45,1826.31 227.45,1856.31 227.45,2236.31 254.45,2263.31 413.45,2263.31
FUSE_VBUS on SSTXRX1 "SSTXRX1_FUSE_VBUS_P104" (solid, remove dead copper, pour order 104): 547.45,2345.31 547.45,2280.31 550.45,2277.31 581.45,2277.31 583.45,2279.31 583.45,2302.31 559.45,2326.31 559.45,2345.31
FUSE_VBUS on SSTXRX1 "SSTXRX1_FUSE_VBUS_P102" (solid, remove dead copper, pour order 102): 461.45,2344.31 461.45,2280.31 459.45,2278.31 429.45,2278.31 428.45,2279.31 428.45,2305.31 449.45,2326.31 449.45,2343.31
VBUS_SINK on SSTXRX1 "SSTXRX1_VBUS_SINK_P100" (solid, remove dead copper, pour order 100): 583.45,1822.31 583.45,1906.31 578.45,1911.31 549.45,1911.31 545.45,1907.31 545.45,1856.31 553.45,1848.31 553.45,1820.31 556.45,1817.31 578.45,1817.31
PP_HV_SINK on SSTXRX1 "SSTXRX1_PP_HV_SINK_P098" (solid, remove dead copper, pour order 98): 585.45,1820.31 585.45,1848.31 588.45,1851.31 588.45,1907.31 592.45,1911.31 639.45,1911.31 644.45,1906.31 644.45,1850.31 611.45,1817.31 588.45,1817.31
PP_HV_SINK on SSTXRX1 "SSTXRX1_PP_HV_SINK_P096" (solid, remove dead copper, pour order 96): 455.45,1822.31 455.45,1846.31 460.45,1851.31 460.45,1929.31 457.45,1932.31 431.45,1932.31 424.45,1925.31 424.45,1852.31 428.45,1848.31 428.45,1820.31 432.45,1816.31 433.45,1817.31 452.45,1817.31
VBUS_SINK on SSTXRX1 "SSTXRX1_VBUS_SINK_P094" (solid, remove dead copper, pour order 94): 423.45,1906.31 418.45,1911.31 387.45,1911.31 383.45,1907.31 383.45,1832.31 398.45,1817.31 421.45,1817.31 423.45,1819.31
LDO_3V3_SINK on SSTXRX1 "SSTXRX1_LDO_3V3_SINK_P092" (solid, remove dead copper, pour order 92): 521.45,1888.31 487.45,1854.31 477.45,1854.31 477.45,1911.31 507.45,1941.31 517.45,1941.31 521.45,1937.31
GND on Power 1 "POWER_1_GND_P190" (solid, remove dead copper, pour order 190): 0,2700 2080,2700 2080,0 0,0
P3V3 on Power 1 "POWER_1_P3V3_P080" (solid, pour order 80): 1641.93,1424.93 1861,1644 1861,1864 1758,1967 1571.66,1967 1571.66,2015.66 1589.26,2033.26 1624.74,2033.26 1639,2019 1913,2019 2039.66,1892.35 2039.66,1690.66 1684.93,1335.93 1089.66,1335.93 1089.66,1424.93
SYS_PWR on Power 1 "POWER_1_SYS_PWR_P074" (solid, remove dead copper, pour order 74): 1365,732 2072,732 2072,636 1914,478 1365,478
NetC12_1 on Power 1 "POWER_1_NETC12_1_P060" (solid, remove dead copper, pour order 60): 1877,1529.93 2004.66,1529.93 2072,1462.59 2072,889.93 1894.66,889.93 1877,907.59 1877,1203.93
VBUS on Power 1 "POWER_1_VBUS_P050" (solid, remove dead copper, pour order 50): 1383,2013 1383,2134.21 1498.79,2250 1636,2250 1636,2013
P3V3_SINK on Power 1 "POWER_1_P3V3_SINK_P166" (solid, remove dead copper, pour order 166): 0,1146.86 64.45,1211.31 599.45,1211.31 634.45,1176.31 634.45,906.31 264.45,536.31 49.45,536.31 0,585.75
LDO_3V3_SINK on Power 1 "POWER_1_LDO_3V3_SINK_P164" (solid, remove dead copper, pour order 164): 798,2217.75 769.45,2246.31 323.93,2246.31 284.45,2285.79 284.45,2521.31 224.45,2581.31 142.64,2581.31 119.45,2558.12 119.45,1281.31 174.45,1226.31 225.45,1226.31 405.45,1406.31 406.45,1405.31 604.45,1405.31 685,1324.75 685,232.75 726.45,191.31 798,191.31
